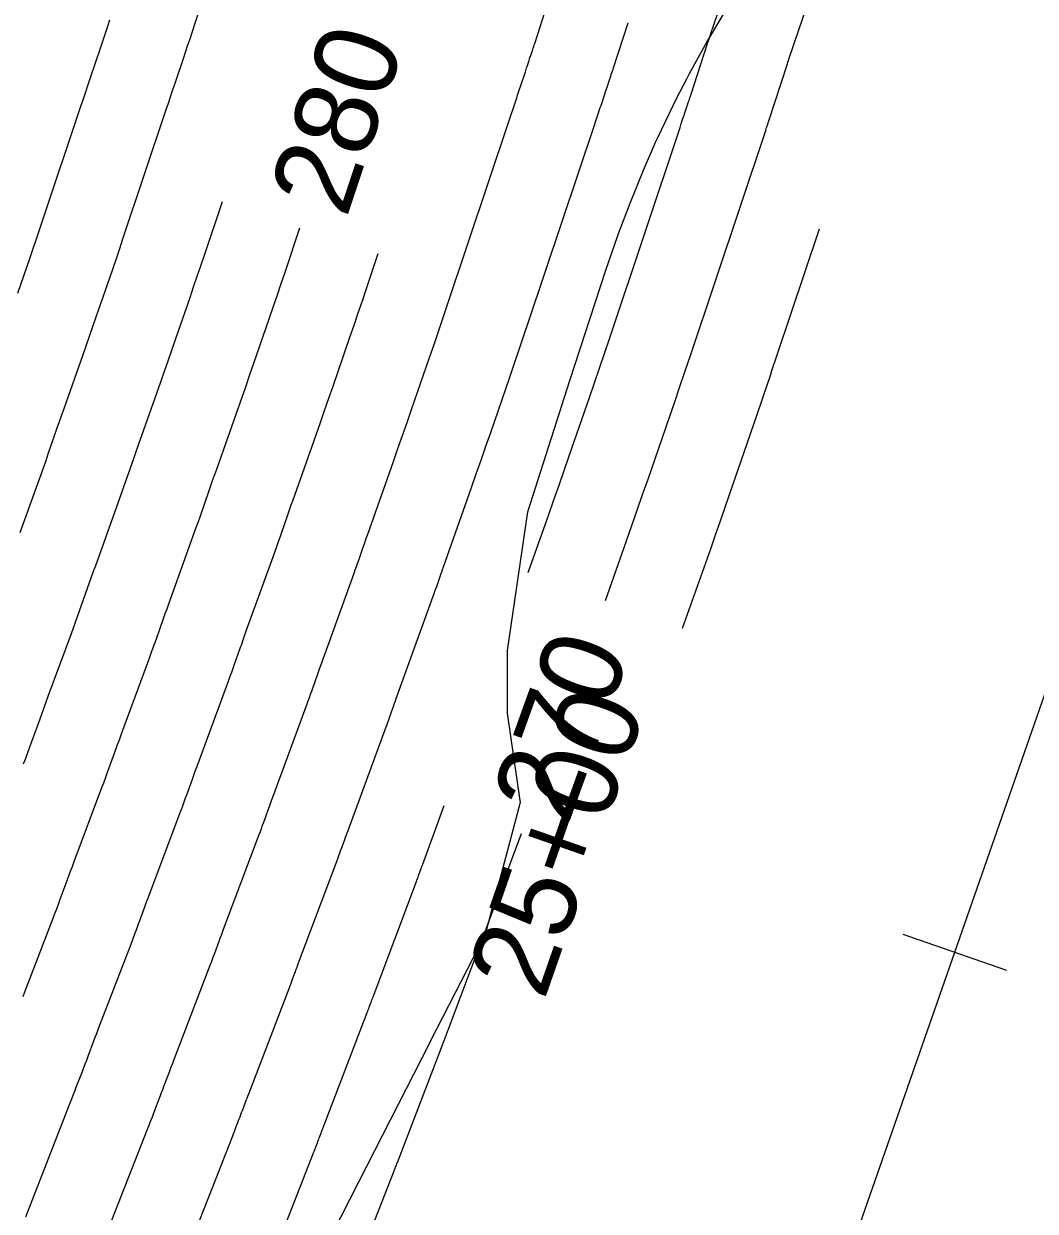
# Model space of a CAD drawing. Extents: x 1710723 to 1713003, y 548603 to 551142.
# Drawn here: x 1712368.6 to 1712442.1, y 549657.6 to 549743.8 of the extents above; entities that cross this region are included whole.
import ezdxf

# ---------------------------------------------------------------- set-up
doc = ezdxf.new("R2010")
doc.units = 0
for name, color, linetype in [('R_Contour Annot', 7, 'Continuous'), ('R_Contours', 7, 'Continuous'), ('R_Horz Alg', 7, 'Continuous'), ('R_Horz Alg Annot', 7, 'Continuous'), ('R_MOT', 7, 'Continuous')]:
    doc.layers.add(name, color=color, linetype=linetype)

msp = doc.modelspace()

# ---------------------------------------------------------------- linework, layer by layer
at = {"layer": 'R_Contours'}
for points in [[(1712405.235, 549703.958), (1712406.726, 549708.178), (1712407.099, 549709.239), (1712407.472, 549710.301), (1712407.842, 549711.363), (1712408.21, 549712.427), (1712409.681, 549716.681), (1712410.047, 549717.745), (1712410.411, 549718.809), (1712410.771, 549719.875), (1712411.13, 549720.942), (1712416.265, 549736.298), (1712416.295, 549736.386), (1712416.324, 549736.474), (1712416.354, 549736.562), (1712416.383, 549736.65), (1712416.503, 549737.005), (1712416.532, 549737.091), (1712416.561, 549737.177), (1712416.59, 549737.264), (1712416.619, 549737.35), (1712416.765, 549737.792), (1712416.778, 549737.831), (1712416.79, 549737.869), (1712416.803, 549737.908), (1712416.816, 549737.946), (1712416.866, 549738.101), (1712416.878, 549738.139), (1712416.891, 549738.178), (1712416.904, 549738.216), (1712416.917, 549738.255), (1712416.985, 549738.457), (1712417, 549738.503), (1712417.016, 549738.55), (1712417.031, 549738.596), (1712417.046, 549738.643), (1712418.265, 549742.391), (1712418.294, 549742.479), (1712418.323, 549742.567), (1712418.352, 549742.655), (1712418.381, 549742.743), (1712418.498, 549743.096), (1712418.527, 549743.184), (1712418.556, 549743.272), (1712418.585, 549743.36), (1712418.615, 549743.448), (1712420.169, 549748.069)], [(1712410.845, 549701.933), (1712412.371, 549706.254), (1712412.766, 549707.375), (1712413.158, 549708.496), (1712413.549, 549709.618), (1712413.939, 549710.741), (1712415.491, 549715.233), (1712415.878, 549716.356), (1712416.262, 549717.481), (1712416.643, 549718.606), (1712417.021, 549719.732), (1712422.489, 549736.082), (1712422.506, 549736.133), (1712422.523, 549736.185), (1712422.558, 549736.288), (1712422.567, 549736.313), (1712422.575, 549736.339), (1712422.584, 549736.364), (1712422.592, 549736.389), (1712422.638, 549736.529), (1712422.649, 549736.563), (1712422.668, 549736.619), (1712422.675, 549736.642), (1712422.699, 549736.712), (1712422.708, 549736.739), (1712422.717, 549736.766), (1712424.067, 549740.917), (1712424.077, 549740.946), (1712424.086, 549740.975), (1712424.095, 549741.004), (1712424.105, 549741.033), (1712424.143, 549741.148), (1712424.153, 549741.177), (1712424.162, 549741.205), (1712424.172, 549741.234), (1712424.181, 549741.263), (1712425.883, 549746.323)], [(1712368.31, 549706.868), (1712369.687, 549710.687), (1712369.856, 549711.158), (1712370.023, 549711.629), (1712370.189, 549712.102), (1712370.353, 549712.574), (1712371.007, 549714.467), (1712371.171, 549714.94), (1712371.336, 549715.412), (1712371.501, 549715.885), (1712371.668, 549716.357), (1712372.854, 549719.716), (1712373.102, 549720.422), (1712373.35, 549721.127), (1712373.596, 549721.833), (1712373.84, 549722.54), (1712374.818, 549725.367), (1712375.061, 549726.074), (1712375.303, 549726.781), (1712375.542, 549727.489), (1712375.78, 549728.198), (1712378.923, 549737.596), (1712379.078, 549738.058), (1712379.233, 549738.519), (1712379.388, 549738.981), (1712379.544, 549739.442), (1712380.173, 549741.304), (1712380.326, 549741.757), (1712380.478, 549742.211), (1712380.629, 549742.664), (1712380.78, 549743.118), (1712381.547, 549745.437)], [(1712374.486, 549655.659), (1712377.829, 549664.205), (1712377.914, 549664.423), (1712377.999, 549664.641), (1712378.084, 549664.86), (1712378.168, 549665.079), (1712378.508, 549665.965), (1712378.589, 549666.178), (1712378.67, 549666.391), (1712378.751, 549666.605), (1712378.832, 549666.819), (1712379.153, 549667.673), (1712379.233, 549667.887), (1712379.314, 549668.101), (1712379.395, 549668.314), (1712379.477, 549668.527), (1712382.121, 549675.423), (1712382.204, 549675.64), (1712382.286, 549675.857), (1712382.367, 549676.074), (1712382.448, 549676.292), (1712382.769, 549677.164), (1712382.849, 549677.382), (1712382.93, 549677.6), (1712383.011, 549677.818), (1712383.093, 549678.035), (1712385.68, 549684.918), (1712385.764, 549685.144), (1712385.847, 549685.369), (1712385.93, 549685.595), (1712386.012, 549685.821), (1712386.339, 549686.726), (1712386.42, 549686.952), (1712386.502, 549687.178), (1712386.585, 549687.404), (1712386.668, 549687.63), (1712389.166, 549694.414), (1712389.251, 549694.646), (1712389.335, 549694.877), (1712389.418, 549695.108), (1712389.5, 549695.34), (1712389.828, 549696.269), (1712389.91, 549696.5), (1712389.993, 549696.732), (1712390.075, 549696.964), (1712390.159, 549697.196), (1712392.582, 549703.914), (1712392.666, 549704.149), (1712392.75, 549704.385), (1712392.833, 549704.62), (1712392.915, 549704.856), (1712393.241, 549705.8), (1712393.323, 549706.036), (1712393.405, 549706.272), (1712393.487, 549706.507), (1712393.57, 549706.743), (1712395.435, 549712.024), (1712395.767, 549712.966), (1712396.098, 549713.91), (1712396.426, 549714.853), (1712396.754, 549715.798), (1712398.06, 549719.576), (1712398.385, 549720.521), (1712398.708, 549721.467), (1712399.028, 549722.413), (1712399.347, 549723.361), (1712403.818, 549736.731), (1712403.889, 549736.943), (1712403.96, 549737.156), (1712404.032, 549737.368), (1712404.104, 549737.581), (1712404.393, 549738.438), (1712404.464, 549738.646), (1712404.534, 549738.855), (1712404.603, 549739.064), (1712404.673, 549739.273), (1712405.026, 549740.341), (1712405.056, 549740.434), (1712405.087, 549740.527), (1712405.117, 549740.62), (1712405.148, 549740.713), (1712405.269, 549741.086), (1712405.3, 549741.179), (1712405.33, 549741.273), (1712405.361, 549741.366), (1712405.392, 549741.459), (1712405.556, 549741.947), (1712405.594, 549742.059), (1712405.631, 549742.171), (1712405.669, 549742.284), (1712405.705, 549742.396), (1712406.662, 549745.337)], [(1712374.807, 549744.079), (1712374.636, 549743.564), (1712374.464, 549743.049), (1712374.292, 549742.535), (1712374.118, 549742.021), (1712373.404, 549739.908), (1712373.227, 549739.384), (1712373.051, 549738.86), (1712372.875, 549738.336), (1712372.699, 549737.812), (1712369.889, 549729.408), (1712369.671, 549728.759), (1712369.451, 549728.11), (1712369.23, 549727.462), (1712369.007, 549726.814), (1712368.112, 549724.225)], [(1712412.464, 549743.864), (1712411.376, 549740.52), (1712411.35, 549740.44), (1712411.324, 549740.361), (1712411.297, 549740.281), (1712411.271, 549740.202), (1712411.155, 549739.857), (1712411.133, 549739.791), (1712411.111, 549739.725), (1712411.089, 549739.659), (1712411.067, 549739.594), (1712410.982, 549739.33), (1712410.96, 549739.264), (1712410.939, 549739.198), (1712410.917, 549739.132), (1712410.895, 549739.066), (1712410.646, 549738.312), (1712410.597, 549738.164), (1712410.548, 549738.016), (1712410.498, 549737.869), (1712410.448, 549737.721), (1712410.243, 549737.115), (1712410.193, 549736.965), (1712410.142, 549736.815), (1712410.092, 549736.665), (1712410.041, 549736.515), (1712405.238, 549722.151), (1712404.9, 549721.144), (1712404.559, 549720.138), (1712404.216, 549719.133), (1712403.87, 549718.128), (1712402.482, 549714.112), (1712402.134, 549713.108), (1712401.785, 549712.105), (1712401.433, 549711.103), (1712401.08, 549710.101), (1712399.046, 549704.339), (1712398.984, 549704.163), (1712398.922, 549703.986), (1712398.86, 549703.81), (1712398.799, 549703.633), (1712398.555, 549702.926), (1712398.494, 549702.75), (1712398.432, 549702.573), (1712398.369, 549702.397), (1712398.306, 549702.221), (1712395.621, 549694.777), (1712395.559, 549694.606), (1712395.498, 549694.434), (1712395.437, 549694.262), (1712395.376, 549694.09), (1712395.133, 549693.402), (1712395.072, 549693.23), (1712395.01, 549693.059), (1712394.948, 549692.887), (1712394.885, 549692.716), (1712392.115, 549685.194), (1712392.055, 549685.029), (1712391.995, 549684.864), (1712391.935, 549684.699), (1712391.875, 549684.534), (1712391.636, 549683.873), (1712391.577, 549683.708), (1712391.516, 549683.543), (1712391.455, 549683.378), (1712391.394, 549683.213), (1712388.524, 549675.577), (1712388.466, 549675.421), (1712388.408, 549675.266), (1712388.35, 549675.11), (1712388.292, 549674.954), (1712388.063, 549674.331), (1712388.005, 549674.175), (1712387.947, 549674.02), (1712387.888, 549673.864), (1712387.829, 549673.709), (1712384.892, 549666.05), (1712384.835, 549665.9), (1712384.777, 549665.749), (1712384.72, 549665.599), (1712384.664, 549665.448), (1712384.437, 549664.846), (1712384.381, 549664.696), (1712384.324, 549664.545), (1712384.267, 549664.395), (1712384.209, 549664.245), (1712383.97, 549663.62), (1712383.91, 549663.466), (1712383.851, 549663.312), (1712383.791, 549663.159), (1712383.731, 549663.005), (1712380.287, 549654.199)], [(1712382.98, 549730.899), (1712381.672, 549726.989), (1712381.414, 549726.22), (1712381.154, 549725.453), (1712380.892, 549724.685), (1712380.628, 549723.919), (1712379.569, 549720.854), (1712379.303, 549720.088), (1712379.037, 549719.323), (1712378.769, 549718.558), (1712378.499, 549717.793), (1712377.143, 549713.953), (1712376.998, 549713.54), (1712376.853, 549713.127), (1712376.709, 549712.714), (1712376.566, 549712.3), (1712375.994, 549710.645), (1712375.85, 549710.231), (1712375.705, 549709.818), (1712375.558, 549709.406), (1712375.41, 549708.993), (1712373.772, 549704.45), (1712373.624, 549704.039), (1712373.477, 549703.627), (1712373.33, 549703.216), (1712373.184, 549702.804), (1712372.602, 549701.155), (1712372.456, 549700.743), (1712372.308, 549700.331), (1712372.159, 549699.921), (1712372.009, 549699.51), (1712370.325, 549694.939), (1712370.175, 549694.53), (1712370.026, 549694.122), (1712369.878, 549693.713), (1712369.73, 549693.304), (1712369.139, 549691.667), (1712368.991, 549691.258), (1712368.841, 549690.849), (1712368.69, 549690.441), (1712368.538, 549690.034)], [(1712368.517, 549673.142), (1712368.647, 549673.481), (1712370.705, 549678.849), (1712370.835, 549679.19), (1712370.964, 549679.531), (1712371.092, 549679.873), (1712371.218, 549680.215), (1712371.722, 549681.584), (1712371.849, 549681.926), (1712371.976, 549682.268), (1712372.103, 549682.61), (1712372.231, 549682.952), (1712374.252, 549688.329), (1712374.382, 549688.676), (1712374.51, 549689.023), (1712374.637, 549689.37), (1712374.764, 549689.718), (1712375.266, 549691.111), (1712375.392, 549691.459), (1712375.518, 549691.807), (1712375.645, 549692.155), (1712375.773, 549692.502), (1712377.728, 549697.812), (1712377.856, 549698.162), (1712377.984, 549698.513), (1712378.11, 549698.865), (1712378.235, 549699.217), (1712378.732, 549700.625), (1712378.857, 549700.977), (1712378.982, 549701.329), (1712379.108, 549701.681), (1712379.234, 549702.032), (1712381.134, 549707.3), (1712381.261, 549707.653), (1712381.387, 549708.007), (1712381.511, 549708.361), (1712381.634, 549708.715), (1712382.124, 549710.133), (1712382.247, 549710.488), (1712382.37, 549710.842), (1712382.494, 549711.196), (1712382.619, 549711.55), (1712384.145, 549715.87), (1712384.435, 549716.694), (1712384.724, 549717.518), (1712385.011, 549718.343), (1712385.297, 549719.169), (1712386.439, 549722.471), (1712386.723, 549723.297), (1712387.005, 549724.124), (1712387.285, 549724.951), (1712387.563, 549725.78), (1712388.643, 549729.008)], [(1712416.454, 549699.908), (1712418.136, 549704.669), (1712418.492, 549705.68), (1712418.846, 549706.692), (1712419.199, 549707.704), (1712419.55, 549708.717), (1712421.875, 549715.444), (1712421.997, 549715.797), (1712422.117, 549716.151), (1712422.237, 549716.505), (1712422.356, 549716.859), (1712422.83, 549718.277), (1712422.949, 549718.631), (1712423.068, 549718.986), (1712423.187, 549719.34), (1712423.306, 549719.694), (1712426.413, 549728.92)], [(1712394.307, 549727.118), (1712393.455, 549724.57), (1712393.157, 549723.682), (1712392.857, 549722.795), (1712392.554, 549721.909), (1712392.249, 549721.024), (1712391.025, 549717.483), (1712390.719, 549716.598), (1712390.411, 549715.714), (1712390.101, 549714.83), (1712389.79, 549713.947), (1712388.095, 549709.146), (1712387.991, 549708.852), (1712387.887, 549708.557), (1712387.785, 549708.262), (1712387.682, 549707.967), (1712387.274, 549706.786), (1712387.172, 549706.49), (1712387.068, 549706.196), (1712386.964, 549705.901), (1712386.858, 549705.607), (1712384.696, 549699.614), (1712384.592, 549699.322), (1712384.487, 549699.031), (1712384.383, 549698.739), (1712384.28, 549698.447), (1712383.867, 549697.279), (1712383.764, 549696.987), (1712383.659, 549696.695), (1712383.554, 549696.404), (1712383.447, 549696.113), (1712381.22, 549690.066), (1712381.115, 549689.78), (1712381.01, 549689.493), (1712380.906, 549689.206), (1712380.802, 549688.919), (1712380.388, 549687.77), (1712380.284, 549687.483), (1712380.179, 549687.196), (1712380.073, 549686.91), (1712379.966, 549686.624), (1712377.662, 549680.493), (1712377.557, 549680.214), (1712377.453, 549679.934), (1712377.349, 549679.654), (1712377.246, 549679.374), (1712376.833, 549678.254), (1712376.73, 549677.974), (1712376.625, 549677.694), (1712376.519, 549677.415), (1712376.413, 549677.136), (1712374.062, 549671.004), (1712373.956, 549670.728), (1712373.851, 549670.452), (1712373.746, 549670.175), (1712373.642, 549669.898), (1712373.226, 549668.791), (1712373.122, 549668.514), (1712373.017, 549668.237), (1712372.912, 549667.961), (1712372.806, 549667.685), (1712372.366, 549666.537), (1712372.257, 549666.253), (1712372.147, 549665.97), (1712372.037, 549665.687), (1712371.927, 549665.404), (1712368.686, 549657.119)], [(1712386.087, 549652.739), (1712389.633, 549661.805), (1712389.668, 549661.894), (1712389.703, 549661.984), (1712389.737, 549662.073), (1712389.772, 549662.162), (1712389.911, 549662.525), (1712389.944, 549662.612), (1712389.977, 549662.699), (1712390.01, 549662.787), (1712390.043, 549662.874), (1712390.175, 549663.224), (1712390.208, 549663.311), (1712390.241, 549663.398), (1712390.274, 549663.486), (1712390.307, 549663.573), (1712393.537, 549671.996), (1712393.573, 549672.089), (1712393.608, 549672.183), (1712393.643, 549672.276), (1712393.678, 549672.37), (1712393.815, 549672.744), (1712393.85, 549672.838), (1712393.885, 549672.932), (1712393.92, 549673.025), (1712393.955, 549673.118), (1712397.108, 549681.508), (1712397.146, 549681.612), (1712397.185, 549681.716), (1712397.223, 549681.82), (1712397.261, 549681.924), (1712397.411, 549682.341), (1712397.449, 549682.445), (1712397.487, 549682.549), (1712397.525, 549682.654), (1712397.563, 549682.758), (1712399.134, 549687.023)], [(1712391.887, 549651.279), (1712395.535, 549660.605), (1712395.545, 549660.63), (1712395.555, 549660.655), (1712395.564, 549660.68), (1712395.574, 549660.704), (1712395.612, 549660.805), (1712395.622, 549660.829), (1712395.631, 549660.853), (1712395.64, 549660.878), (1712395.649, 549660.902), (1712395.685, 549660.999), (1712395.695, 549661.023), (1712395.704, 549661.047), (1712395.713, 549661.071), (1712395.722, 549661.096), (1712399.245, 549670.283), (1712399.257, 549670.314), (1712399.269, 549670.345), (1712399.281, 549670.377), (1712399.292, 549670.408), (1712399.339, 549670.534), (1712399.35, 549670.566), (1712399.362, 549670.597), (1712399.374, 549670.629), (1712399.386, 549670.66), (1712402.822, 549679.803), (1712402.838, 549679.846), (1712402.854, 549679.889), (1712402.869, 549679.932), (1712402.885, 549679.976), (1712402.947, 549680.149), (1712402.963, 549680.192), (1712402.979, 549680.235), (1712402.995, 549680.278), (1712403.01, 549680.321), (1712404.734, 549685.002)]]:
    msp.add_lwpolyline(points, dxfattribs=at)
at = {"layer": 'R_Horz Alg'}
msp.add_line((1712378.285, 549510.238), (1712448.881, 549712.659), dxfattribs=at)
at = {"layer": 'R_Horz Alg Annot'}
msp.add_lwpolyline([(1712432.449, 549677.69), (1712440.003, 549675.056)], dxfattribs=at)
at = {"layer": 'R_MOT'}
msp.add_lwpolyline([(1712388.348, 549650.708), (1712392.929, 549659.701), (1712397.519, 549668.691), (1712398.593, 549670.793), (1712402.116, 549677.678), (1712404.673, 549687.281), (1712404.658, 549687.383), (1712403.721, 549693.736), (1712403.731, 549698.296), (1712405.194, 549708.377), (1712408.263, 549717.897), (1712410.876, 549725.913), (1712411.719, 549728.361), (1712411.805, 549728.598), (1712412.634, 549730.784), (1712413.616, 549733.181), (1712414.518, 549735.266), (1712414.652, 549735.558), (1712415.771, 549737.899), (1712416.02, 549738.395), (1712416.761, 549739.832), (1712416.96, 549740.207), (1712418.217, 549742.479), (1712419.543, 549744.714)], dxfattribs=at)

# ---------------------------------------------------------------- texts
at = {"layer": 'R_Contour Annot'}
for s, rotation, p in [('280', 71.5417, (1712392.012, 549729.627)), ('270', 70.15392, (1712408.117, 549685.539))]:
    msp.add_text(s, height=6, rotation=rotation, dxfattribs=at).set_placement(p)
at = {"layer": 'R_Horz Alg Annot'}
msp.add_text('25+00', height=6, rotation=70.7734, dxfattribs=at).set_placement((1712406.384, 549672.796))

doc.saveas('drawing.dxf')
